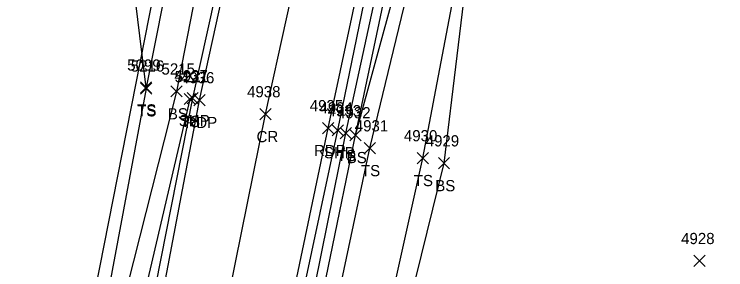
# Model space of a CAD drawing. Extents: x 1601151 to 1602912, y 499508 to 501770.
# Drawn here: x 1601442.9 to 1601569.7, y 501438 to 501483.6 of the extents above; entities that cross this region are included whole.
import ezdxf

# ---------------------------------------------------------------- set-up
doc = ezdxf.new("R2010")
doc.units = 0
for name, color, linetype in [('L_A', 7, 'Continuous'), ('L_I', 7, 'Continuous'), ('L_TIC', 7, 'Continuous'), ('LELB', 7, 'Continuous'), ('P_A', 7, 'Continuous'), ('P_I', 7, 'Continuous'), ('P_TIC', 7, 'Continuous'), ('PET', 7, 'Continuous'), ('PRC', 7, 'Continuous'), ('PSP', 7, 'Continuous'), ('UCO', 7, 'Continuous')]:
    doc.layers.add(name, color=color, linetype=linetype)

msp = doc.modelspace()

# ---------------------------------------------------------------- linework, layer by layer
at = {"layer": 'L_TIC'}
for points in [[(1601465.41, 501469.49), (1601467.41, 501471.49)], [(1601467.41, 501469.49), (1601465.41, 501471.49)], [(1601465.41, 501469.49), (1601467.41, 501471.49)], [(1601467.41, 501469.49), (1601465.41, 501471.49)], [(1601465.44, 501469.32), (1601467.44, 501471.32)], [(1601467.44, 501469.32), (1601465.44, 501471.32)], [(1601470.86, 501468.79), (1601472.86, 501470.79)], [(1601472.86, 501468.79), (1601470.86, 501470.79)], [(1601473.21, 501467.43), (1601475.21, 501469.43)], [(1601475.21, 501467.43), (1601473.21, 501469.43)], [(1601501.01, 501461.34), (1601503.01, 501463.34)], [(1601503.01, 501461.34), (1601501.01, 501463.34)], [(1601502.71, 501460.98), (1601504.71, 501462.98)], [(1601504.71, 501460.98), (1601502.71, 501462.98)], [(1601502.71, 501460.98), (1601504.71, 501462.98)], [(1601504.71, 501460.98), (1601502.71, 501462.98)], [(1601505.28, 501458.65), (1601507.28, 501460.65)], [(1601507.28, 501458.65), (1601505.28, 501460.65)], [(1601514.69, 501456.88), (1601516.69, 501458.88)], [(1601516.69, 501456.88), (1601514.69, 501458.88)], [(1601518.48, 501455.97), (1601520.48, 501457.97)], [(1601520.48, 501455.97), (1601518.48, 501457.97)], [(1601563.97, 501438.54), (1601565.97, 501440.54)], [(1601565.97, 501438.54), (1601563.97, 501440.54)]]:
    msp.add_lwpolyline(points, dxfattribs=at)
at = {"layer": 'LELB'}
for points in [[(1601499.92, 501604), (1601490.36, 501558.83), (1601481.52, 501519.51), (1601471.86, 501469.79), (1601460.93, 501426.61), (1601455.31, 501410.23), (1601445.3, 501379.66), (1601439.18, 501348.77), (1601435.26, 501335.89), (1601429.53, 501329.54), (1601421.05, 501325.23), (1601398.76, 501317.23), (1601349.97, 501319.48), (1601303.09, 501322.98), (1601268.06, 501324.06)], [(1601496.02, 501601.36), (1601492.25, 501599.82), (1601484.89, 501560.66), (1601477.13, 501522.17), (1601472.69, 501502.03), (1601466.41, 501470.49), (1601466.44, 501470.32), (1601458.39, 501426.99), (1601455.31, 501410.23), (1601450.82, 501378.69), (1601446.59, 501347.41), (1601443.46, 501338.36), (1601436.17, 501327.92), (1601429.34, 501322.98), (1601421.93, 501316.54), (1601411.85, 501313.01), (1601398.09, 501312.69), (1601349.98, 501315.61), (1601303.17, 501320.06), (1601267.61, 501322.07)], [(1601476.49, 501304.53), (1601478.93, 501340.78), (1601483.82, 501372.17), (1601493.27, 501419.11), (1601502.01, 501462.34), (1601513.24, 501514.09), (1601519.29, 501544.8)], [(1601486.02, 501263.27), (1601481.25, 501258.66), (1601479.54, 501258.59), (1601479.12, 501258.61), (1601477.94, 501258.85), (1601480.43, 501300.77), (1601480.94, 501334.18), (1601485.69, 501371.5), (1601485.76, 501372.59), (1601494.84, 501418.67), (1601503.71, 501461.98), (1601514.66, 501513.83), (1601522.81, 501541.12), (1601521.69, 501544.36)], [(1601485.76, 501372.59), (1601497.57, 501418.45), (1601506.28, 501459.65), (1601515.17, 501496.54), (1601521.49, 501515.23), (1601526.08, 501542.78), (1601521.69, 501544.36), (1601519.29, 501544.8)], [(1601503.71, 501461.98), (1601517.9, 501514.09), (1601522.81, 501541.12)], [(1601498.2, 501377.8), (1601500.67, 501388.74), (1601509.41, 501415.97), (1601519.48, 501456.97), (1601526.43, 501514.5)], [(1601500.67, 501388.74), (1601506.54, 501416.64), (1601515.69, 501457.88), (1601526.43, 501514.5)], [(1601466.41, 501470.49), (1601462.4, 501503.57)], [(1601474.21, 501468.43), (1601464.37, 501426.19), (1601452.79, 501377.97), (1601448.85, 501346.81), (1601446.07, 501336.34), (1601438.08, 501325.89), (1601430.89, 501319.18), (1601421.93, 501316.54)], [(1601474.72, 501468.58), (1601474.21, 501468.43)]]:
    msp.add_lwpolyline(points, dxfattribs=at)
at = {"layer": 'P_TIC'}
for points in [[(1601473.72, 501467.58), (1601475.72, 501469.58)], [(1601475.72, 501467.58), (1601473.72, 501469.58)], [(1601474.95, 501467.24), (1601476.95, 501469.24)], [(1601476.95, 501467.24), (1601474.95, 501469.24)], [(1601486.67, 501464.73), (1601488.67, 501466.73)], [(1601488.67, 501464.73), (1601486.67, 501466.73)], [(1601497.83, 501462.24), (1601499.83, 501464.24)], [(1601499.83, 501462.24), (1601497.83, 501464.24)], [(1601499.56, 501461.85), (1601501.56, 501463.85)], [(1601501.56, 501461.85), (1601499.56, 501463.85)]]:
    msp.add_lwpolyline(points, dxfattribs=at)
at = {"layer": 'PET'}
for points in [[(1601544.22, 500876.26), (1601539.18, 500895.59), (1601526.95, 500943.37), (1601516.32, 500985.83), (1601505.44, 501027.92), (1601495.1, 501070.93), (1601487, 501107.14), (1601479.48, 501143.91), (1601474.16, 501178.21), (1601471.72, 501199.66), (1601469.2, 501232.53), (1601470.85, 501304.37), (1601475.76, 501342.26), (1601481.23, 501372.74), (1601489.71, 501419.6), (1601498.83, 501463.24), (1601509.83, 501514.72), (1601518.29, 501552.56), (1601529.19, 501602.72), (1601530.09, 501606.93), (1601533.57, 501622.36), (1601544.66, 501669.88)], [(1601523.48, 500870.9), (1601505.84, 500938.64), (1601494.52, 500981.09), (1601483.99, 501022.88), (1601473.44, 501065.01), (1601465.15, 501101.36), (1601457.99, 501138.15), (1601451.8, 501174.88), (1601449.08, 501198.01), (1601446.66, 501230.72), (1601445.89, 501253.39), (1601447.49, 501294.25), (1601451.95, 501334.78), (1601458.71, 501377.25), (1601475.95, 501468.24), (1601495.79, 501558.68), (1601503.76, 501593.61), (1601511.67, 501629.01)]]:
    msp.add_lwpolyline(points, dxfattribs=at)
at = {"layer": 'PRC'}
msp.add_lwpolyline([(1601533.3, 500873.43), (1601528.2, 500892.93), (1601515.88, 500940.69), (1601516.09, 500940.41), (1601505.08, 500982.8), (1601494.07, 501025.46), (1601483.89, 501067.42), (1601475.63, 501103.84), (1601468.62, 501140.87), (1601462.9, 501176.52), (1601460.41, 501198.76), (1601457.83, 501229.92), (1601457.03, 501256.97), (1601458.23, 501305.06), (1601463.89, 501343.75), (1601469.52, 501375.72), (1601487.67, 501465.73), (1601498.93, 501516.84), (1601507.24, 501554.65), (1601515.35, 501591.13), (1601523.43, 501627.3), (1601533.11, 501671.57)], dxfattribs=at)
at = {"layer": 'PSP'}
for points in [[(1601528.9, 500943.6), (1601517.98, 500986.13), (1601507.44, 501028.32), (1601496.62, 501071.21), (1601488.24, 501107.28), (1601480.68, 501144.12), (1601475.12, 501178.17), (1601472.51, 501199.52), (1601470.88, 501228.6), (1601471.76, 501230.34), (1601469.82, 501257.16), (1601471.6, 501304.23), (1601477.35, 501341.75), (1601482.3, 501372.17), (1601491.34, 501419.44), (1601500.56, 501462.85), (1601511.15, 501514.36), (1601520.07, 501552.2), (1601531.25, 501603.07), (1601534.57, 501619.48), (1601535.23, 501620.04), (1601536.15, 501623.42), (1601535.02, 501624.1), (1601546.22, 501669.66)], [(1601388.17, 501311.14), (1601412.26, 501309.02), (1601423.07, 501312.07), (1601431.46, 501316.65), (1601439.53, 501323.6), (1601447.66, 501332.4), (1601449.11, 501334.88), (1601456.83, 501377.63), (1601474.72, 501468.58), (1601494.61, 501558.74), (1601502.13, 501593.71), (1601501.84, 501601.9), (1601507.35, 501629.07)]]:
    msp.add_lwpolyline(points, dxfattribs=at)
at = {"layer": 'UCO'}
msp.add_lwpolyline([(1601766.65, 501489.44), (1601471.02, 501503.9), (1601438.7, 501339.97), (1601411.28, 501184.01), (1601489.93, 500928.89)], dxfattribs=at)

# ---------------------------------------------------------------- texts
at = {"layer": 'L_A'}
for s, p in [('TS', (1601464.82, 501465.49)), ('TS', (1601464.82, 501465.49)), ('TS', (1601464.85, 501465.32)), ('BS', (1601470.3, 501464.79)), ('TS', (1601472.61, 501463.43)), ('TS', (1601500.42, 501457.34)), ('BS', (1601502.16, 501456.98)), ('BS', (1601502.16, 501456.98)), ('TS', (1601504.69, 501454.65)), ('TS', (1601514.1, 501452.88)), ('BS', (1601517.92, 501451.97))]:
    msp.add_text(s, height=2, dxfattribs=at).set_placement(p)
at = {"layer": 'L_I'}
for s, p in [('5099', (1601463.06, 501473.49)), ('5099', (1601463.06, 501473.49)), ('5216', (1601463.7, 501473.32)), ('5215', (1601469.17, 501472.79)), ('5221', (1601471.51, 501471.43)), ('4933', (1601498.75, 501465.34)), ('4932', (1601500.45, 501464.98)), ('4932', (1601500.45, 501464.98)), ('4931', (1601503.59, 501462.65)), ('4930', (1601512.34, 501460.88)), ('4929', (1601516.22, 501459.97)), ('4928', (1601561.71, 501442.54))]:
    msp.add_text(s, height=2, dxfattribs=at).set_placement(p)
at = {"layer": 'P_A'}
for s, p in [('SHP', (1601472.26, 501463.58)), ('RDP', (1601473.44, 501463.24)), ('CR', (1601486.1, 501460.73)), ('RDP', (1601496.32, 501458.24)), ('SHP', (1601498.1, 501457.85))]:
    msp.add_text(s, height=2, dxfattribs=at).set_placement(p)
at = {"layer": 'P_I'}
for s, p in [('4937', (1601471.46, 501471.58)), ('4936', (1601472.63, 501471.24)), ('4938', (1601484.41, 501468.73)), ('4935', (1601495.57, 501466.24)), ('4934', (1601497.3, 501465.85))]:
    msp.add_text(s, height=2, dxfattribs=at).set_placement(p)

doc.saveas('drawing.dxf')
